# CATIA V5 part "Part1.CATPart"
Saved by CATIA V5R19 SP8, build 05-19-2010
Part number: Bati
Bounding box of the stored display mesh (mm): x 0 to 0, y -286 to 500, z -325 to 195
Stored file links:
  G:\EU_thinkMotion\CFAO_2010\MMS_groupe1\MMS_groupe1\OK\ppiault\piault\piault_cfao\Part1.CATPart
  D:\Catia\Finaltest.CATProduct
  G:\EU_thinkMotion\CFAO_2010\MMS_groupe1\MMS_groupe1\OK\ppiault\piault\piault_cfao\Part2.CATPart
  G:\EU_thinkMotion\CFAO_2010\MMS_groupe1\MMS_groupe1\OK\ppiault\piault\piault_cfao\Part3.CATPart
  G:\Catia Projet\CFAO2\Product2.CATProduct
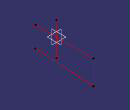
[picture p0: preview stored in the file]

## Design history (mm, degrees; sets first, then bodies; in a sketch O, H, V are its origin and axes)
External parameters (linked from other documents)
  External.DiametreRabatteur = 400 mm
Set1
  Point1 to Point6: linked copy from another document
Set2
  Line1: type PtPt, FirstPoint Point1, SecondPoint Point2, End 500 {= External.DiametreRabatteur +100mm}
  Line2: type PtPt, FirstPoint Point3, SecondPoint Point4
  Line3: type PtDir, LineSecondUpto vertex of Line1, RefPoint Point4, Direction xy-plane, Start 0, End 20
  Line4: type PtPt, FirstPoint Point5, SecondPoint Point6
Body1 (main body)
